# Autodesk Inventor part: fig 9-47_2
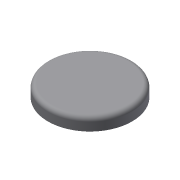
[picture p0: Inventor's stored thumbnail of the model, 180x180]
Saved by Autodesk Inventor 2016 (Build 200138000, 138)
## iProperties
Created: 2013-03
Part Number: fig 9-47_2
Material: Generic
Document SubType Name: Modeling
Designer: CADCIM
Density: 1 g/cm^3
Appearance: Default
Author: CADCIM
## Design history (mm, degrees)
sketch "Sketch1"
  geometry: C1 r 2.5 at (0, 0); 1 further point
  constraints: 1 centre point, 1 coincident
  dimensions: "d0" = 5 diameter of C1
extrude "Extrusion1" new body sketch "Sketch1" distance "d2" = 0.75; taper "d3" = 0 deg
fillet "Fillet1" dims "d4" = 0.25
body "Solid1"
